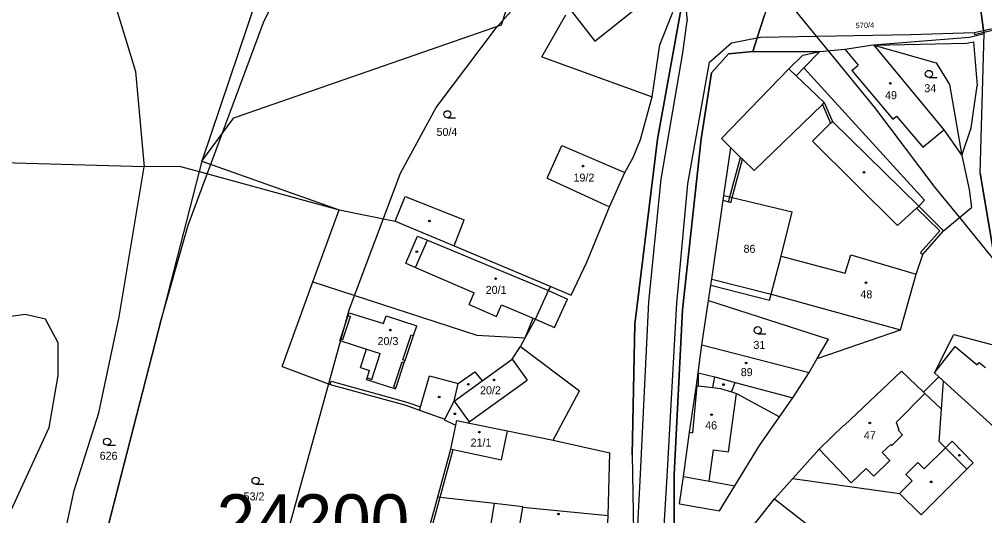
# Model space of a CAD drawing. Extents: x -725765 to -723182, y -1052705 to -1049154.
# Drawn here: x -724945.7 to -724740.7, y -1050771.8 to -1050666.3 of the extents above; entities that cross this region are included whole.
import ezdxf

# ---------------------------------------------------------------- set-up
doc = ezdxf.new("R2010")
doc.units = 0
for name, color, linetype in [('Vrstva 1', 7, 'Continuous'), ('Vrstva 18', 7, 'Continuous'), ('Vrstva 19', 7, 'Continuous'), ('Vrstva 25', 7, 'Continuous'), ('Vrstva 4', 7, 'Continuous'), ('Vrstva 52', 7, 'Continuous'), ('Vrstva 53', 7, 'Continuous')]:
    doc.layers.add(name, color=color, linetype=linetype)

msp = doc.modelspace()

# ---------------------------------------------------------------- linework, layer by layer
at = {"layer": 'Vrstva 1'}
for points in [[(-724883.7, -1050627.32), (-724906.96, -1050696.43)], [(-724930.87, -1050645), (-724921.08, -1050677.38)], [(-724843.32, -1050667.46), (-724839.04, -1050654.16)], [(-724810.21, -1050691.79), (-724804.75, -1050661.51)], [(-724741.93, -1050661.51), (-724740.98, -1050668.64)], [(-724834.79, -1050674.23), (-724829.67, -1050665.31)], [(-724809.73, -1050671.72), (-724806.96, -1050664.76)], [(-724789.04, -1050670.2), (-724787.52, -1050665.42)], [(-724900.17, -1050687.2), (-724843.32, -1050667.46)], [(-724743.99, -1050670.08), (-724740.89, -1050669.34)], [(-724741.74, -1050698.99), (-724740.89, -1050669.34)], [(-724740.98, -1050668.64), (-724740.93, -1050669.04)], [(-724740.93, -1050669.04), (-724740.89, -1050669.34)], [(-724789.99, -1050673.16), (-724789.04, -1050670.2)], [(-724764.4, -1050671.69), (-724743.99, -1050670.08)], [(-724811.34, -1050682.75), (-724809.73, -1050671.72)], [(-724798.75, -1050677.64), (-724795.12, -1050673.64)], [(-724795.12, -1050673.64), (-724789.99, -1050673.16)], [(-724789.99, -1050673.16), (-724775.73, -1050673.15)], [(-724779.13, -1050676.6), (-724775.73, -1050673.15)], [(-724775.73, -1050673.15), (-724770.45, -1050672.63)], [(-724770.45, -1050672.63), (-724764.4, -1050671.69)], [(-724764.4, -1050671.69), (-724764.29, -1050671.82)], [(-724764.29, -1050671.82), (-724749.39, -1050689.76)], [(-724764.29, -1050671.82), (-724751.04, -1050675.55)], [(-724834.79, -1050674.23), (-724811.34, -1050682.75)], [(-724751.04, -1050675.55), (-724748.24, -1050680.15)], [(-724921.08, -1050677.38), (-724919.24, -1050697.62)], [(-724800.93, -1050691.71), (-724798.75, -1050677.64)], [(-724796.64, -1050691.63), (-724782.34, -1050676.78)], [(-724782.34, -1050676.78), (-724780.78, -1050678.28)], [(-724780.78, -1050678.28), (-724779.13, -1050676.6)], [(-724779.13, -1050676.6), (-724753.54, -1050704.74)], [(-724748.24, -1050680.15), (-724745.63, -1050695.25)], [(-724813.8, -1050691.81), (-724811.34, -1050682.75)], [(-724906.96, -1050696.43), (-724900.17, -1050687.2)], [(-724749.39, -1050689.76), (-724745.63, -1050695.25)], [(-724815.41, -1050695.62), (-724813.8, -1050691.81)], [(-724815, -1050731.09), (-724810.21, -1050691.79)], [(-724804.92, -1050728), (-724800.93, -1050691.71)], [(-724796.64, -1050691.63), (-724794.62, -1050693.61)], [(-724833.65, -1050700.07), (-724830.51, -1050693.13)], [(-724830.51, -1050693.13), (-724817.18, -1050698.83)], [(-724796.1, -1050703.71), (-724794.62, -1050693.61)], [(-724919.24, -1050697.62), (-724971.87, -1050696.18)], [(-724817.18, -1050698.83), (-724815.41, -1050695.62)], [(-724745.63, -1050695.25), (-724744.03, -1050702.42)], [(-724924.55, -1050729.47), (-724919.24, -1050697.62)], [(-724911.52, -1050697.54), (-724919.24, -1050697.62)], [(-724911.52, -1050697.54), (-724907.53, -1050698.63)], [(-724906.96, -1050696.43), (-724907.53, -1050698.63)], [(-724906.96, -1050696.43), (-724877.81, -1050706.76)], [(-724907.53, -1050698.63), (-724939.59, -1050823.52)], [(-724833.65, -1050700.07), (-724821.35, -1050705.7)], [(-724820.44, -1050706.11), (-724817.18, -1050698.83)], [(-724741.74, -1050698.99), (-724738.17, -1050719.97)], [(-724796.25, -1050704.72), (-724796.1, -1050703.71)], [(-724796.1, -1050703.71), (-724794.86, -1050704.01)], [(-724794.86, -1050704.01), (-724794.37, -1050704.13)], [(-724794.37, -1050704.13), (-724781.61, -1050707.22)], [(-724744.03, -1050702.42), (-724743.55, -1050706.28)], [(-724825.22, -1050717.89), (-724820.44, -1050706.11)], [(-724821.35, -1050705.7), (-724820.44, -1050706.11)], [(-724798.71, -1050721.53), (-724796.25, -1050704.72)], [(-724754.76, -1050705.98), (-724753.54, -1050704.74)], [(-724754.76, -1050705.98), (-724749.46, -1050711.22)], [(-724749.46, -1050711.22), (-724743.55, -1050706.28)], [(-724883.37, -1050722.06), (-724877.81, -1050706.76)], [(-724877.81, -1050706.76), (-724865.89, -1050709.2)], [(-724783.95, -1050716.61), (-724781.61, -1050707.22)], [(-724865.89, -1050709.2), (-724853.4, -1050714.44)], [(-724753.91, -1050716.24), (-724749.46, -1050711.22)], [(-724853.4, -1050714.44), (-724832.87, -1050723.06)], [(-724786.1, -1050724.72), (-724783.95, -1050716.61)], [(-724755.27, -1050720.41), (-724753.91, -1050716.24)], [(-724828.56, -1050724.87), (-724825.22, -1050717.89)], [(-724758.61, -1050732.29), (-724755.27, -1050720.41)], [(-724889.9, -1050740.07), (-724883.37, -1050722.06)], [(-724883.37, -1050722.06), (-724848.57, -1050733.39)], [(-724799.42, -1050726.06), (-724798.91, -1050722.77)], [(-724798.91, -1050722.77), (-724798.71, -1050721.53)], [(-724798.91, -1050722.77), (-724786.46, -1050725.96)], [(-724836.13, -1050730), (-724833.33, -1050723.89)], [(-724833.33, -1050723.89), (-724832.87, -1050723.06)], [(-724832.87, -1050723.06), (-724828.56, -1050724.87)], [(-724786.46, -1050725.96), (-724786.1, -1050724.72)], [(-724800.81, -1050735.43), (-724799.42, -1050726.06)], [(-724799.42, -1050726.06), (-724773.9, -1050734.26)], [(-724806.68, -1050763.03), (-724804.92, -1050728)], [(-724928.86, -1050749.87), (-724924.55, -1050729.47)], [(-724838.33, -1050733.95), (-724836.13, -1050730)], [(-724815.58, -1050758.85), (-724815, -1050731.09)], [(-724776.34, -1050738.38), (-724758.61, -1050732.29)], [(-724848.57, -1050733.39), (-724838.33, -1050733.95)], [(-724839.33, -1050735.84), (-724838.33, -1050733.95)], [(-724776.34, -1050738.38), (-724773.9, -1050734.26)], [(-724751.42, -1050741.41), (-724747.3, -1050733.24)], [(-724747.3, -1050733.24), (-724737.14, -1050735.96)], [(-724841.09, -1050738.51), (-724839.33, -1050735.84)], [(-724801.57, -1050741.38), (-724800.81, -1050735.43)], [(-724800.81, -1050735.43), (-724778, -1050741.32)], [(-724847.43, -1050743.12), (-724841.09, -1050738.51)], [(-724841.09, -1050738.51), (-724837.89, -1050742.95)], [(-724778, -1050741.32), (-724776.34, -1050738.38)], [(-724889.9, -1050740.07), (-724879.72, -1050743.86)], [(-724781.48, -1050746.68), (-724778, -1050741.32)], [(-724770.56, -1050752.61), (-724758.39, -1050741.04)], [(-724758.39, -1050741.04), (-724753.75, -1050745.52)], [(-724853.36, -1050747.41), (-724847.43, -1050743.12)], [(-724850.19, -1050751.82), (-724837.89, -1050742.95)], [(-724801.97, -1050744.12), (-724801.57, -1050741.38)], [(-724751.42, -1050741.41), (-724750.5, -1050742.25)], [(-724750.5, -1050742.25), (-724749.48, -1050743.18)], [(-724749.92, -1050749.11), (-724749.48, -1050743.18)], [(-724749.48, -1050743.18), (-724728.86, -1050761.96)], [(-724879.72, -1050743.86), (-724863.67, -1050748.28)], [(-724803.44, -1050754.03), (-724801.97, -1050744.12)], [(-724801.97, -1050744.12), (-724801.77, -1050744.14)], [(-724801.77, -1050744.14), (-724801.56, -1050744.16)], [(-724801.56, -1050744.16), (-724798.47, -1050744.49)], [(-724798.47, -1050744.49), (-724796.82, -1050744.74)], [(-724796.82, -1050744.74), (-724794.49, -1050745.45)], [(-724855.4, -1050751.23), (-724853.36, -1050747.41)], [(-724794.49, -1050745.45), (-724793.46, -1050745.77)], [(-724793.46, -1050745.77), (-724784.3, -1050750.73)], [(-724784.3, -1050750.73), (-724781.48, -1050746.68)], [(-724753.75, -1050745.52), (-724753.44, -1050745.82)], [(-724753.44, -1050745.82), (-724749.92, -1050749.11)], [(-724863.67, -1050748.28), (-724860.73, -1050749.33)], [(-724860.73, -1050749.33), (-724855.4, -1050751.23)], [(-724750.43, -1050755.98), (-724749.92, -1050749.11)], [(-724934.06, -1050766.42), (-724928.86, -1050749.87)], [(-724855.5, -1050751.37), (-724855.4, -1050751.23)], [(-724855.5, -1050751.37), (-724853.02, -1050752.49)], [(-724853.02, -1050752.49), (-724852.83, -1050751.55)], [(-724852.83, -1050751.55), (-724850.48, -1050752.03)], [(-724788.58, -1050756.81), (-724784.3, -1050750.73)], [(-724854.07, -1050757.61), (-724853.02, -1050752.49)], [(-724850.48, -1050752.03), (-724850.19, -1050751.82)], [(-724850.48, -1050752.03), (-724842.08, -1050753.73)], [(-724775.9, -1050757.63), (-724770.62, -1050752.55)], [(-724770.62, -1050752.55), (-724770.56, -1050752.61)], [(-724842.08, -1050753.73), (-724832.37, -1050755.68)], [(-724832.37, -1050755.68), (-724820.32, -1050758.38)], [(-724804.71, -1050763.4), (-724803.44, -1050754.03)], [(-724856.84, -1050767.77), (-724854.07, -1050757.61)], [(-724793.79, -1050765.43), (-724788.58, -1050756.81)], [(-724781.48, -1050763.84), (-724775.9, -1050757.63)], [(-724750.43, -1050755.98), (-724749.09, -1050757.32)], [(-724749.09, -1050757.32), (-724744.55, -1050761.86)], [(-724820.69, -1050771.71), (-724820.32, -1050758.38)], [(-724815.58, -1050758.85), (-724815.13, -1050787.45)], [(-724806.76, -1050807.12), (-724806.68, -1050763.03)], [(-724804.71, -1050763.4), (-724799.27, -1050764.38)], [(-724785.4, -1050768.2), (-724781.48, -1050763.84)], [(-724781.48, -1050763.84), (-724758.84, -1050767.03)], [(-724754.21, -1050771.6), (-724744.55, -1050761.86)], [(-724799.27, -1050764.38), (-724793.79, -1050765.43)], [(-724937.04, -1050780.19), (-724934.06, -1050766.42)], [(-724863.55, -1050792.32), (-724856.84, -1050767.77)], [(-724856.84, -1050767.77), (-724856.34, -1050767.83)], [(-724856.34, -1050767.83), (-724844.85, -1050769.12)], [(-724758.84, -1050767.03), (-724754.21, -1050771.6)], [(-724845.67, -1050774.3), (-724844.85, -1050769.12)], [(-724839.65, -1050774.99), (-724838.84, -1050769.93)], [(-724838.84, -1050769.93), (-724820.69, -1050771.71)], [(-724790.16, -1050774.29), (-724785.4, -1050768.2)], [(-724785.4, -1050768.2), (-724776.03, -1050775.48)], [(-724820.89, -1050776.23), (-724820.69, -1050771.71)]]:
    msp.add_lwpolyline(points, dxfattribs=at)
at = {"layer": 'Vrstva 25'}
for points in [[(-724752.6, -1050678.64), (-724750.85, -1050678.64)], [(-724854.83, -1050687.21), (-724853.08, -1050687.21)], [(-724788.93, -1050733.09), (-724787.18, -1050733.09)], [(-724927.07, -1050756.77), (-724925.32, -1050756.77)], [(-724895.56, -1050765.05), (-724893.81, -1050765.05)]]:
    msp.add_lwpolyline(points, dxfattribs=at)
for centre, radius in [((-724752.6, -1050677.89), 0.75), ((-724760.77, -1050679.91), 0.175), ((-724854.83, -1050686.46), 0.75), ((-724826.03, -1050697.48), 0.175), ((-724766.38, -1050698.77), 0.175), ((-724858.63, -1050709.14), 0.175), ((-724861.33, -1050715.67), 0.175), ((-724844.58, -1050721.38), 0.175), ((-724765.96, -1050722.27), 0.175), ((-724866.95, -1050732.32), 0.175), ((-724788.93, -1050732.34), 0.75), ((-724791.39, -1050739.3), 0.175), ((-724844.94, -1050742.89), 0.175), ((-724850.38, -1050743.83), 0.175), ((-724796.2, -1050743.89), 0.175), ((-724856.56, -1050746.52), 0.175), ((-724853.26, -1050750.11), 0.175), ((-724798.74, -1050750.28), 0.175), ((-724765.14, -1050752.04), 0.175), ((-724927.07, -1050756.02), 0.75), ((-724848.05, -1050753.99), 0.175), ((-724746.13, -1050758.9), 0.175), ((-724895.56, -1050764.3), 0.75), ((-724752.11, -1050764.56), 0.175), ((-724831.24, -1050771.39), 0.175)]:
    msp.add_circle(centre, radius, dxfattribs=at)
at = {"layer": 'Vrstva 4'}
for points in [[(-724804.69, -1050658.92), (-724803.94, -1050666.63)], [(-724828.51, -1050664.57), (-724823.53, -1050670.92)], [(-724823.53, -1050670.92), (-724814.9, -1050664.09)], [(-724804.81, -1050673.38), (-724803.94, -1050666.63)], [(-724740.98, -1050668.64), (-724734.13, -1050667.09)], [(-724740.93, -1050669.04), (-724734.08, -1050667.49)], [(-724788.35, -1050670.06), (-724756.47, -1050669.52)], [(-724756.47, -1050669.52), (-724742.99, -1050669.1)], [(-724742.99, -1050669.1), (-724740.98, -1050668.64)], [(-724742.99, -1050669.1), (-724742.9, -1050669.49)], [(-724742.9, -1050669.49), (-724740.93, -1050669.04)], [(-724799.18, -1050675.39), (-724794.52, -1050671.27)], [(-724794.52, -1050671.27), (-724789.04, -1050670.2)], [(-724789.04, -1050670.2), (-724788.35, -1050670.06)], [(-724764.29, -1050671.82), (-724744.59, -1050671.37)], [(-724744.59, -1050671.37), (-724743.1, -1050671.1)], [(-724743.1, -1050671.1), (-724742.33, -1050680.45)], [(-724809.42, -1050700.22), (-724804.81, -1050673.38)], [(-724779.36, -1050673.91), (-724775.73, -1050673.15)], [(-724770.45, -1050672.63), (-724767.58, -1050676.03)], [(-724803.78, -1050701.28), (-724799.18, -1050675.39)], [(-724782.34, -1050676.78), (-724779.36, -1050673.91)], [(-724768.92, -1050677.16), (-724767.58, -1050676.03)], [(-724768.92, -1050677.16), (-724760.26, -1050687.53)], [(-724780.78, -1050678.28), (-724774.83, -1050683.99)], [(-724743.63, -1050689.33), (-724742.33, -1050680.45)], [(-724789.7, -1050698.44), (-724775.21, -1050684.36)], [(-724775.21, -1050684.36), (-724774.83, -1050683.99)], [(-724775.21, -1050684.36), (-724773.45, -1050688.39)], [(-724774.83, -1050683.99), (-724773.07, -1050688.02)], [(-724773.45, -1050688.39), (-724773.07, -1050688.02)], [(-724773.07, -1050688.02), (-724754.76, -1050705.98)], [(-724760.26, -1050687.53), (-724759.48, -1050686.87)], [(-724759.48, -1050686.87), (-724753.85, -1050693.49)], [(-724777.28, -1050692.19), (-724773.45, -1050688.39)], [(-724753.85, -1050693.49), (-724749.39, -1050689.76)], [(-724745.63, -1050695.25), (-724743.63, -1050689.33)], [(-724794.62, -1050693.61), (-724792.57, -1050695.62)], [(-724777.28, -1050692.19), (-724759.27, -1050710.12)], [(-724794.86, -1050704.01), (-724792.57, -1050695.62)], [(-724794.37, -1050704.13), (-724792.16, -1050696.02)], [(-724792.57, -1050695.62), (-724792.16, -1050696.02)], [(-724792.16, -1050696.02), (-724789.7, -1050698.44)], [(-724907.53, -1050698.63), (-724877.81, -1050706.76)], [(-724812.07, -1050726.3), (-724809.42, -1050700.22)], [(-724806.14, -1050726.63), (-724803.78, -1050701.28)], [(-724865.89, -1050709.2), (-724863.79, -1050703.97)], [(-724863.79, -1050703.97), (-724851.27, -1050708.91)], [(-724795.15, -1050705.08), (-724794.86, -1050704.01)], [(-724794.67, -1050705.23), (-724794.37, -1050704.13)], [(-724796.25, -1050704.72), (-724795.15, -1050705.08)], [(-724795.15, -1050705.08), (-724794.67, -1050705.23)], [(-724759.27, -1050710.12), (-724755.2, -1050706.39)], [(-724755.2, -1050706.39), (-724754.76, -1050705.98)], [(-724755.2, -1050706.39), (-724750.29, -1050711.25)], [(-724853.4, -1050714.44), (-724851.27, -1050708.91)], [(-724863.67, -1050718.1), (-724861.19, -1050712.34)], [(-724861.19, -1050712.34), (-724859.08, -1050713.21)], [(-724754.36, -1050715.84), (-724750.29, -1050711.25)], [(-724861.57, -1050719.01), (-724859.08, -1050713.21)], [(-724859.08, -1050713.21), (-724833.33, -1050723.89)], [(-724783.95, -1050716.61), (-724770.34, -1050720.24)], [(-724770.34, -1050720.24), (-724769.2, -1050716.35)], [(-724769.2, -1050716.35), (-724755.27, -1050720.41)], [(-724754.36, -1050715.84), (-724753.91, -1050716.24)], [(-724863.67, -1050718.1), (-724861.57, -1050719.01)], [(-724861.57, -1050719.01), (-724849.13, -1050724.43)], [(-724798.71, -1050721.53), (-724786.1, -1050724.72)], [(-724850.19, -1050726.88), (-724849.13, -1050724.43)], [(-724833.33, -1050723.89), (-724829.36, -1050725.75)], [(-724786.1, -1050724.72), (-724758.61, -1050732.29)], [(-724850.19, -1050726.88), (-724844.4, -1050729.41)], [(-724844.4, -1050729.41), (-724843.32, -1050726.92)], [(-724843.32, -1050726.92), (-724836.59, -1050729.81)], [(-724832.12, -1050731.79), (-724829.36, -1050725.75)], [(-724813.82, -1050762.96), (-724812.07, -1050726.3)], [(-724808.16, -1050763.42), (-724806.14, -1050726.63)], [(-724875.86, -1050729.25), (-724875.66, -1050728.64)], [(-724875.66, -1050728.64), (-724868.36, -1050730.95)], [(-724877.52, -1050734.18), (-724875.86, -1050729.25)], [(-724877.02, -1050734.34), (-724875.37, -1050729.41)], [(-724875.86, -1050729.25), (-724875.37, -1050729.41)], [(-724868.36, -1050730.95), (-724867.83, -1050729.27)], [(-724867.83, -1050729.27), (-724861.35, -1050731.42)], [(-724838.33, -1050733.95), (-724836.59, -1050729.81)], [(-724836.59, -1050729.81), (-724836.13, -1050730)], [(-724836.13, -1050730), (-724832.12, -1050731.79)], [(-724862.05, -1050733.49), (-724861.35, -1050731.42)], [(-724877.63, -1050734.51), (-724877.52, -1050734.18)], [(-724877.63, -1050734.51), (-724871.98, -1050736.37)], [(-724877.52, -1050734.18), (-724877.02, -1050734.34)], [(-724864.31, -1050738.63), (-724862.54, -1050733.33)], [(-724863.82, -1050738.79), (-724862.05, -1050733.49)], [(-724862.54, -1050733.33), (-724862.05, -1050733.49)], [(-724873.25, -1050740.24), (-724871.98, -1050736.37)], [(-724871.98, -1050736.37), (-724869.1, -1050737.31)], [(-724839.33, -1050735.84), (-724826.79, -1050745.21)], [(-724751.42, -1050741.41), (-724747.01, -1050735.81)], [(-724747.01, -1050735.81), (-724742.33, -1050739.68)], [(-724870.9, -1050742.8), (-724869.1, -1050737.31)], [(-724866.2, -1050744.35), (-724864.46, -1050739.06)], [(-724865.73, -1050744.51), (-724863.99, -1050739.23)], [(-724864.46, -1050739.06), (-724863.99, -1050739.23)], [(-724864.31, -1050738.63), (-724863.82, -1050738.79)], [(-724863.99, -1050739.23), (-724863.82, -1050738.79)], [(-724742.33, -1050739.68), (-724741.92, -1050739.17)], [(-724741.92, -1050739.17), (-724740.6, -1050740.24)], [(-724873.25, -1050740.24), (-724871.35, -1050740.87)], [(-724871.88, -1050742.48), (-724871.35, -1050740.87)], [(-724852.53, -1050743.67), (-724849.03, -1050741.17)], [(-724849.03, -1050741.17), (-724847.43, -1050743.12)], [(-724879.72, -1050743.86), (-724879.53, -1050743.18)], [(-724879.53, -1050743.18), (-724863.47, -1050747.61)], [(-724871.98, -1050742.79), (-724871.88, -1050742.48)], [(-724871.98, -1050742.79), (-724865.82, -1050744.81)], [(-724871.88, -1050742.48), (-724870.9, -1050742.8)], [(-724860.54, -1050748.65), (-724858.65, -1050742.02)], [(-724858.65, -1050742.02), (-724852.53, -1050743.67)], [(-724801.57, -1050741.38), (-724801.56, -1050744.16)], [(-724801.57, -1050741.38), (-724798.04, -1050742.28)], [(-724798.47, -1050744.49), (-724798.04, -1050742.28)], [(-724798.04, -1050742.28), (-724793.74, -1050743.45)], [(-724753.75, -1050745.52), (-724750.5, -1050742.25)], [(-724866.2, -1050744.35), (-724865.73, -1050744.51)], [(-724865.82, -1050744.81), (-724865.73, -1050744.51)], [(-724853.36, -1050747.41), (-724852.53, -1050743.67)], [(-724832.37, -1050755.68), (-724826.79, -1050745.21)], [(-724802.74, -1050754.13), (-724801.77, -1050744.14)], [(-724794.49, -1050745.45), (-724793.74, -1050743.45)], [(-724793.74, -1050743.45), (-724781.48, -1050746.68)], [(-724853.36, -1050747.41), (-724850.19, -1050751.82)], [(-724795.11, -1050758.19), (-724793.46, -1050745.77)], [(-724759.52, -1050751.98), (-724753.44, -1050745.82)], [(-724863.47, -1050747.61), (-724860.54, -1050748.65)], [(-724860.73, -1050749.33), (-724860.54, -1050748.65)], [(-724759.52, -1050751.98), (-724759.01, -1050753.43)], [(-724759.15, -1050753.57), (-724759.01, -1050753.43)], [(-724759.15, -1050753.57), (-724758.2, -1050754.55)], [(-724843.33, -1050759.89), (-724842.08, -1050753.73)], [(-724803.44, -1050754.03), (-724802.74, -1050754.13)], [(-724760.43, -1050756.84), (-724758.2, -1050754.55)], [(-724856.34, -1050767.83), (-724853.58, -1050757.71)], [(-724854.07, -1050757.61), (-724853.58, -1050757.71)], [(-724853.58, -1050757.71), (-724843.33, -1050759.89)], [(-724775.9, -1050757.63), (-724769.12, -1050764.79)], [(-724762.48, -1050758.31), (-724760.65, -1050756.6)], [(-724760.65, -1050756.6), (-724760.43, -1050756.84)], [(-724753.57, -1050761.79), (-724749.09, -1050757.32)], [(-724749.09, -1050757.32), (-724747.65, -1050755.89)], [(-724747.65, -1050755.89), (-724743.18, -1050760.49)], [(-724799.27, -1050764.38), (-724798.31, -1050757.76)], [(-724798.31, -1050757.76), (-724795.11, -1050758.19)], [(-724762.48, -1050758.31), (-724760.88, -1050760.02)], [(-724769.12, -1050764.79), (-724765.89, -1050761.69)], [(-724765.89, -1050761.69), (-724764.31, -1050763.34)], [(-724764.31, -1050763.34), (-724760.88, -1050760.02)], [(-724757.46, -1050763.03), (-724754.92, -1050760.47)], [(-724754.92, -1050760.47), (-724753.57, -1050761.79)], [(-724744.55, -1050761.86), (-724743.18, -1050760.49)], [(-724815.13, -1050787.45), (-724813.82, -1050762.96)], [(-724809.63, -1050787.94), (-724808.16, -1050763.42)], [(-724805.52, -1050769.23), (-724804.71, -1050763.4)], [(-724757.46, -1050763.03), (-724756.16, -1050764.32)], [(-724797.04, -1050770.75), (-724793.79, -1050765.43)], [(-724758.84, -1050767.03), (-724756.16, -1050764.32)], [(-724863.07, -1050792.46), (-724856.34, -1050767.83)], [(-724844.85, -1050769.12), (-724838.83, -1050769.8)], [(-724838.84, -1050769.93), (-724838.83, -1050769.8)], [(-724805.52, -1050769.23), (-724797.04, -1050770.75)]]:
    msp.add_lwpolyline(points, dxfattribs=at)
at = {"layer": 'Vrstva 52'}
for points in [[(-724954.81, -1050893.27), (-724954.81, -1050889), (-724949.31, -1050865), (-724940.38, -1050827), (-724939.6, -1050823.52), (-724939.59, -1050823.52), (-724915.62, -1050730.13), (-724909.88, -1050710), (-724893.88, -1050667), (-724885.63, -1050650), (-724878.63, -1050642), (-724868.38, -1050635), (-724851.13, -1050625), (-724847.49, -1050622.04), (-724846.02, -1050620.85)], [(-724935.31, -1050936), (-724928.81, -1050929), (-724921.81, -1050914), (-724914.81, -1050892), (-724908.69, -1050863), (-724905.5, -1050842), (-724893.88, -1050794), (-724875.69, -1050728), (-724864.81, -1050699), (-724857.19, -1050685), (-724844.38, -1050668), (-724831.88, -1050654), (-724822.88, -1050647), (-724816.5, -1050644), (-724814.99, -1050644), (-724813.33, -1050644)], [(-724813.33, -1050644), (-724808.37, -1050650.73), (-724806.43, -1050654.63), (-724804.75, -1050661.51), (-724810.21, -1050691.79), (-724815, -1050731.09), (-724815.58, -1050758.85), (-724815.13, -1050787.45), (-724817.4, -1050803.09), (-724819.59, -1050825.69), (-724818.46, -1050833.53), (-724815.27, -1050842.75), (-724807.1, -1050869.67), (-724799.84, -1050887.62), (-724790.58, -1050905.75), (-724781.27, -1050921.4), (-724774.72, -1050931.91), (-724769.97, -1050937.91), (-724755.76, -1050950.09), (-724747.39, -1050955.27), (-724740.23, -1050960.06), (-724733.48, -1050964.31), (-724729, -1050967.94)], [(-724797.81, -1050648.79), (-724786.08, -1050660.92), (-724787.52, -1050665.42), (-724789.04, -1050670.2), (-724789.99, -1050673.16), (-724795.12, -1050673.64), (-724798.75, -1050677.64), (-724800.93, -1050691.71), (-724804.92, -1050728), (-724806.68, -1050763.03), (-724806.76, -1050807.12), (-724807.68, -1050827.87), (-724807.91, -1050834.06), (-724802.7, -1050857.13), (-724793.87, -1050880.36), (-724784.64, -1050902.78), (-724767.07, -1050925.79), (-724749.83, -1050943.31), (-724735.73, -1050952.08), (-724724.93, -1050961.09)], [(-724797.81, -1050648.79), (-724791.63, -1050653), (-724781.31, -1050664), (-724773.97, -1050672.98), (-724764.13, -1050685), (-724751.31, -1050702), (-724746.1, -1050708.41), (-724739.13, -1050717), (-724738.59, -1050717.48)], [(-724738.59, -1050717.48), (-724741.74, -1050698.99), (-724740.89, -1050669.34), (-724740.93, -1050669.04), (-724740.98, -1050668.64), (-724741.93, -1050661.51)], [(-725008.87, -1050841.99), (-725004.69, -1050838), (-725000, -1050833.49), (-724982.88, -1050817), (-724968.81, -1050803), (-724956.13, -1050787), (-724949, -1050774), (-724939.38, -1050753), (-724937.5, -1050742), (-724937.5, -1050735), (-724940.13, -1050730), (-724944.5, -1050729), (-724951.63, -1050730), (-724977.19, -1050734), (-724995.13, -1050740), (-725000, -1050742.11), (-725022.88, -1050752), (-725054.63, -1050765)]]:
    msp.add_lwpolyline(points, dxfattribs=at)

# ---------------------------------------------------------------- texts
at = {"layer": 'Vrstva 18'}
msp.add_text('570/4', height=1.14, rotation=1.9, dxfattribs=at).set_placement((-724768.13, -1050668.19))
for s, p in [('34', (-724753.56, -1050681.78)), ('50/4', (-724857.13, -1050691.06)), ('31', (-724789.85, -1050736.31)), ('626', (-724928.66, -1050759.87)), ('53/2', (-724898.1, -1050768.5))]:
    msp.add_text(s, height=1.7, dxfattribs=at).set_placement(p)
at = {"layer": 'Vrstva 19'}
for s, p in [('49', (-724761.9, -1050683.26)), ('19/2', (-724828.05, -1050700.77)), ('86', (-724791.95, -1050715.9)), ('20/1', (-724846.7, -1050724.63)), ('48', (-724767.14, -1050725.56)), ('20/3', (-724869.66, -1050735.51)), ('89', (-724792.54, -1050742.1)), ('20/2', (-724847.89, -1050745.96)), ('46', (-724800.09, -1050753.39)), ('21/1', (-724849.9, -1050757.06)), ('47', (-724766.41, -1050755.51))]:
    msp.add_text(s, height=1.7, dxfattribs=at).set_placement(p)
at = {"layer": 'Vrstva 53'}
msp.add_text('24200', height=11, dxfattribs=at).set_placement((-724903.83, -1050778.21))

doc.saveas('drawing.dxf')
